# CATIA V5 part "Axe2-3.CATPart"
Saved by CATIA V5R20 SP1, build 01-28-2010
Part number: Axe2-3
Bounding box of the stored display mesh (mm): x 19.524 to 99.814, y 154.083 to 170.718, z -259.809 to -245.185
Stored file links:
  C:\Users\RENARD Simon\Documents\Cours IFMA\2ème année\IAO\Axe2-3.CATPart
  C:\Users\RENARD Simon\Documents\Cours IFMA\2ème année\IAO\Trainattero.CATProduct
  C:\Users\RENARD Simon\Documents\Cours IFMA\2ème année\IAO\Piece2.CATPart
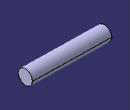
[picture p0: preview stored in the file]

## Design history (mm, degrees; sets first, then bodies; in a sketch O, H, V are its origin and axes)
Set1
  DatumSurface1: linked copy from another document
  Line1: linked copy from another document
Body1 (main body)
  Sketch1 on face of DatumSurface1, origin (96.3114, -1.9724, 0), H (0.0205, 0.9998, 0), V (0, 0, 1)
    circle A1 centre (163.5883, -252.4969) radius 7.5
    point P1 (163.5883, -252.4969)
    reference projected point E1 (163.5883, -252.4969) from Line1
    radius A1 = 7.5
    coincidence: P1 E1
  Pad1: profile Sketch1, direction (-0.9998, 0.0205, 0), length 80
